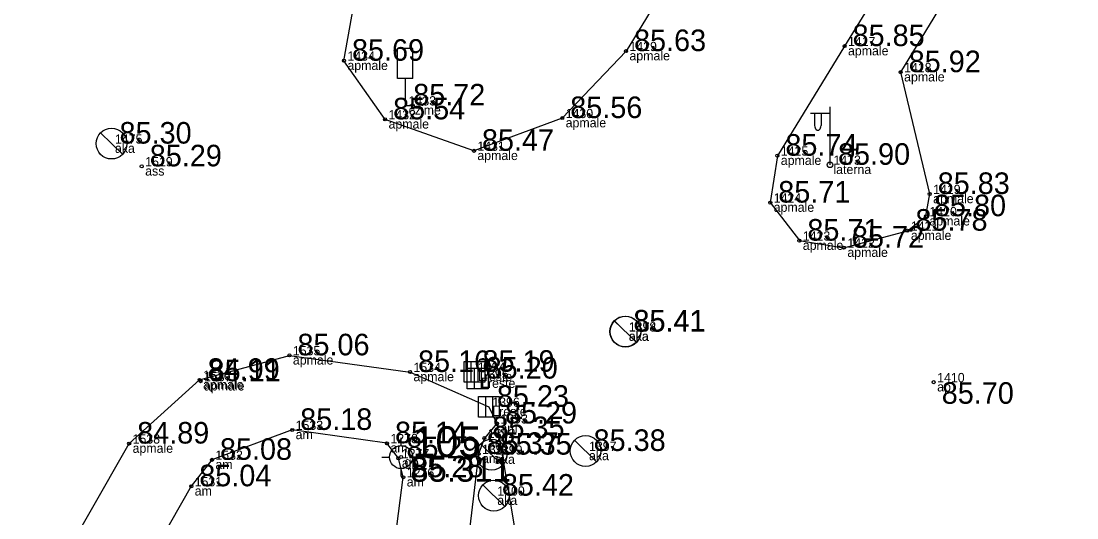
# Model space of a CAD drawing. Extents: x 614911 to 615803, y 262110 to 264311.
# Drawn here: x 615489.87 to 615524.18, y 263504.59 to 263520.72 of the extents above; entities that cross this region are included whole.
import ezdxf

# ---------------------------------------------------------------- set-up
doc = ezdxf.new("R2010")
doc.units = 0
for name, color, linetype in [('Level 12', 7, 'Continuous'), ('Level 16', 7, 'Continuous'), ('Level 19', 7, 'Continuous'), ('Level 37', 7, 'Continuous'), ('Level 44', 7, 'Continuous'), ('Level 48', 7, 'Continuous'), ('Level 53', 7, 'Continuous'), ('Level 54', 7, 'Continuous'), ('Level 57', 7, 'Continuous'), ('Level 58', 7, 'Continuous')]:
    doc.layers.add(name, color=color, linetype=linetype)

msp = doc.modelspace()

# ---------------------------------------------------------------- linework, layer by layer
at = {"layer": 'Level 12'}
for p, q in [((615492.448, 263517.088), (615493.166, 263516.392)), ((615509.143, 263510.988), (615509.861, 263510.292)), ((615509.15, 263510.983), (615509.868, 263510.287)), ((615504.797, 263506.991), (615505.515, 263506.295)), ((615507.852, 263507.11), (615508.57, 263506.414)), ((615504.871, 263505.659), (615505.589, 263504.963))]:
    msp.add_line(p, q, dxfattribs=at)
for centre in [(615492.807, 263516.74), (615509.502, 263510.64), (615509.509, 263510.635), (615508.211, 263506.762), (615505.156, 263506.643), (615505.23, 263505.311)]:
    msp.add_circle(centre, 0.5, dxfattribs=at)
at = {"layer": 'Level 16'}
for p, q in [((615502.595, 263519.825), (615502.095, 263519.825)), ((615502.095, 263518.856), (615502.095, 263519.825)), ((615502.595, 263518.856), (615502.595, 263519.825)), ((615502.595, 263518.856), (615502.095, 263518.856)), ((615502.349, 263518.856), (615502.349, 263517.978)), ((615502.349, 263517.978), (615502.664, 263517.978))]:
    msp.add_line(p, q, dxfattribs=at)
at = {"layer": 'Level 19'}
for p, q in [((615502.217, 263506.938), (615502.217, 263507.188)), ((615501.592, 263506.563), (615501.842, 263506.563)), ((615502.592, 263506.563), (615502.842, 263506.563)), ((615502.217, 263505.938), (615502.217, 263506.188))]:
    msp.add_line(p, q, dxfattribs=at)
for radius in [0.375, 0.05]:
    msp.add_circle((615502.217, 263506.563), radius, dxfattribs=at)
at = {"layer": 'Level 37'}
for points in [[(615516.164, 263530.705), (615512.022, 263523.832), (615509.525, 263519.743), (615507.452, 263517.568), (615504.583, 263516.506), (615501.696, 263517.527), (615500.36, 263519.43), (615500.743, 263521.618), (615509.136, 263535.25)], [(615505.331, 263507.653), (615504.924, 263507.18), (615504.735, 263506.666), (615503.939, 263500.01), (615504.416, 263498.924), (615505.609, 263498.295), (615506.971, 263498.275), (615508.19, 263498.495), (615518.594, 263500.546), (615529.033, 263502.579), (615542.401, 263505.157), (615548.567, 263506.422), (615549.698, 263507.269), (615549.895, 263508.502), (615549.059, 263513.135)], [(615526.135, 263499.075), (615518.177, 263497.544), (615513.224, 263496.283), (615508.96, 263494.354), (615506.959, 263493.391), (615505.012, 263492.643), (615499.231, 263491), (615498.18, 263490.854), (615493.921, 263491.94), (615491.044, 263494.684), (615489.869, 263498.786), (615490.887, 263502.64), (615493.38, 263507.002), (615495.67, 263509.069), (615498.588, 263509.866), (615502.507, 263509.325), (615505.069, 263508.195), (615505.331, 263507.653), (615506.558, 263500.366), (615517.973, 263502.492), (615528.544, 263504.401)]]:
    msp.add_lwpolyline(points, dxfattribs=at)
for points in [[(615520.426, 263524.252), (615519.091, 263523.917), (615516.626, 263519.905), (615514.443, 263516.347), (615514.212, 263514.825), (615515.158, 263513.59), (615516.606, 263513.361), (615518.67, 263513.913), (615519.271, 263514.382), (615519.393, 263515.104), (615518.45, 263519.058), (615520.777, 263522.869)], [(615498.678, 263507.445), (615496.07, 263506.474), (615495.398, 263505.615), (615493.067, 263501.527), (615492.502, 263500.109), (615492.417, 263497.555), (615492.947, 263496.239), (615493.327, 263495.784), (615494.541, 263495.306), (615496.067, 263495.065), (615499.6, 263495.729), (615500.442, 263496.233), (615501.164, 263497.228), (615502.288, 263505.909), (615502.129, 263506.525), (615501.758, 263507.012)]]:
    msp.add_lwpolyline(points, close=True, dxfattribs=at)
at = {"layer": 'Level 44'}
for p, q in [((615516.153, 263516.052), (615516.153, 263517.935)), ((615516.153, 263517.715), (615515.518, 263517.715)), ((615515.653, 263517.715), (615515.653, 263517.323)), ((615515.863, 263517.715), (615515.863, 263517.323))]:
    msp.add_line(p, q, dxfattribs=at)
msp.add_circle((615516.153, 263516.052), 0.09, dxfattribs=at)
msp.add_ellipse((615515.758, 263517.323), major_axis=(0, 0.151), ratio=0.695971, start_param=1.570796, end_param=4.712389, dxfattribs=at)
at = {"layer": 'Level 48'}
for p, q in [((615504.487, 263509.671), (615504.487, 263508.996)), ((615504.712, 263509.671), (615504.712, 263508.996)), ((615504.591, 263509.449), (615504.591, 263508.774)), ((615504.816, 263509.449), (615504.816, 263508.774)), ((615504.956, 263508.533), (615504.956, 263507.858)), ((615505.181, 263508.533), (615505.181, 263507.858))]:
    msp.add_line(p, q, dxfattribs=at)
for points in [[(615504.262, 263509.671), (615504.937, 263509.671), (615504.937, 263508.996), (615504.262, 263508.996)], [(615504.366, 263509.449), (615505.041, 263509.449), (615505.041, 263508.774), (615504.366, 263508.774)], [(615504.731, 263508.533), (615505.406, 263508.533), (615505.406, 263507.858), (615504.731, 263507.858)]]:
    msp.add_lwpolyline(points, close=True, dxfattribs=at)
at = {"layer": 'Level 57'}
for centre in [(615516.626, 263519.905), (615509.525, 263519.743), (615500.36, 263519.43), (615518.45, 263519.058), (615501.696, 263517.527), (615507.452, 263517.568), (615504.583, 263516.506), (615514.443, 263516.347), (615493.789, 263516.001), (615519.393, 263515.104), (615514.212, 263514.825), (615519.271, 263514.382), (615518.67, 263513.913), (615515.158, 263513.59), (615516.606, 263513.361), (615498.588, 263509.866), (615502.507, 263509.325), (615495.67, 263509.069), (615495.7, 263509.025), (615519.524, 263508.994), (615505.331, 263507.653), (615498.678, 263507.445), (615504.924, 263507.18), (615493.38, 263507.002), (615501.758, 263507.012), (615502.129, 263506.525), (615504.735, 263506.666), (615496.07, 263506.474), (615502.288, 263505.909), (615495.398, 263505.615)]:
    msp.add_circle(centre, 0.05, dxfattribs=at)
at = {"layer": 'Level 58'}
for centre in [(615516.626, 263519.905), (615509.525, 263519.743), (615500.36, 263519.43), (615518.45, 263519.058), (615501.696, 263517.527), (615507.452, 263517.568), (615504.583, 263516.506), (615514.443, 263516.347), (615493.789, 263516.001), (615519.393, 263515.104), (615514.212, 263514.825), (615519.271, 263514.382), (615518.67, 263513.913), (615515.158, 263513.59), (615516.606, 263513.361), (615498.588, 263509.866), (615502.507, 263509.325), (615495.67, 263509.069), (615495.7, 263509.025), (615519.524, 263508.994), (615505.331, 263507.653), (615498.678, 263507.445), (615504.924, 263507.18), (615493.38, 263507.002), (615501.758, 263507.012), (615502.129, 263506.525), (615504.735, 263506.666), (615496.07, 263506.474), (615502.288, 263505.909), (615495.398, 263505.615)]:
    msp.add_circle(centre, 0.05, dxfattribs=at)

# ---------------------------------------------------------------- texts
at = {"layer": 'Level 19'}
for s, height, p in [(' 105', 1, (615502.217, 263506.563)), (' 85.311', 0.8, (615502.217, 263505.763))]:
    msp.add_text(s, height=height, dxfattribs=at).set_placement(p)
at = {"layer": 'Level 48'}
for s, p in [(' 85.19', (615504.6, 263509.333)), (' 85.20', (615504.704, 263509.111)), (' 85.23', (615505.069, 263508.195))]:
    msp.add_text(s, height=0.7, dxfattribs=at).set_placement(p)
at = {"layer": 'Level 53'}
for s, p in [(' apmale', (615516.626, 263519.605)), (' apmale', (615509.525, 263519.443)), (' apmale', (615500.36, 263519.13)), (' apmale', (615518.45, 263518.758)), (' czime', (615502.349, 263517.678)), (' apmale', (615501.696, 263517.227)), (' apmale', (615507.452, 263517.268)), (' aka', (615492.807, 263516.44)), (' apmale', (615504.583, 263516.206)), (' apmale', (615514.443, 263516.047)), (' ass', (615493.789, 263515.701)), (' laterna', (615516.153, 263515.752)), (' apmale', (615519.393, 263514.804)), (' apmale', (615514.212, 263514.525)), (' apmale', (615519.271, 263514.082)), (' apmale', (615518.67, 263513.613)), (' apmale', (615515.158, 263513.29)), (' apmale', (615516.606, 263513.061)), (' aka', (615509.502, 263510.34)), (' aka', (615509.509, 263510.335)), (' apmale', (615498.588, 263509.566)), (' apmale', (615502.507, 263509.025)), (' Lreste', (615504.6, 263509.033)), (' apmale', (615495.67, 263508.769)), (' apmale', (615495.7, 263508.725)), (' Lreste', (615504.704, 263508.811)), (' ap', (615519.524, 263508.694)), (' Lreste', (615505.069, 263507.895)), (' am', (615505.331, 263507.353)), (' am', (615498.678, 263507.145)), (' apmale', (615493.38, 263506.702)), (' am', (615501.758, 263506.712)), (' am', (615504.924, 263506.88)), (' am', (615504.735, 263506.366)), (' aka', (615505.156, 263506.343)), (' aka', (615508.211, 263506.462)), (' am', (615496.07, 263506.174)), (' am', (615502.129, 263506.225)), (' gp', (615502.217, 263506.263)), (' am', (615502.288, 263505.609)), (' am', (615495.398, 263505.315)), (' aka', (615505.23, 263505.011))]:
    msp.add_text(s, height=0.3, dxfattribs=at).set_placement(p)
at = {"layer": 'Level 54'}
for s, p in [(' 1429', (615509.525, 263519.743)), (' 1417', (615516.626, 263519.905)), (' 1434', (615500.36, 263519.43)), (' 1418', (615518.45, 263519.058)), (' 1433', (615502.349, 263517.978)), (' 1430', (615507.452, 263517.568)), (' 1432', (615501.696, 263517.527)), (' 1475', (615492.807, 263516.74)), (' 1431', (615504.583, 263516.506)), (' 1425', (615514.443, 263516.347)), (' 1519', (615493.789, 263516.001)), (' 1473', (615516.153, 263516.052)), (' 1424', (615514.212, 263514.825)), (' 1419', (615519.393, 263515.104)), (' 1420', (615519.271, 263514.382)), (' 1421', (615518.67, 263513.913)), (' 1423', (615515.158, 263513.59)), (' 1422', (615516.606, 263513.361)), (' 1398', (615509.502, 263510.64)), (' 1474', (615509.509, 263510.635)), (' 1535', (615498.588, 263509.866)), (' 1534', (615502.507, 263509.325)), (' 1394', (615504.6, 263509.333)), (' 1536', (615495.67, 263509.069)), (' 1537', (615495.7, 263509.025)), (' 1395', (615504.704, 263509.111)), (' 1410', (615519.524, 263508.994)), (' 1396', (615505.069, 263508.195)), (' 1393', (615505.331, 263507.653)), (' 1533', (615498.678, 263507.445)), (' 1538', (615493.38, 263507.002)), (' 1278', (615501.758, 263507.012)), (' 1392', (615504.924, 263507.18)), (' 1391', (615504.735, 263506.666)), (' 1399', (615505.156, 263506.643)), (' 1397', (615508.211, 263506.762)), (' 1532', (615496.07, 263506.474)), (' 1277', (615502.129, 263506.525)), (' 1276', (615502.288, 263505.909)), (' 1531', (615495.398, 263505.615)), (' 1400', (615505.23, 263505.311))]:
    msp.add_text(s, height=0.3, dxfattribs=at).set_placement(p)
at = {"layer": 'Level 58'}
for s, p in [(' 85.85', (615516.626, 263519.905)), (' 85.63', (615509.525, 263519.743)), (' 85.69', (615500.36, 263519.43)), (' 85.92', (615518.45, 263519.058)), (' 85.72', (615502.349, 263517.978)), (' 85.54', (615501.696, 263517.527)), (' 85.56', (615507.452, 263517.568)), (' 85.30', (615492.807, 263516.74)), (' 85.47', (615504.583, 263516.506)), (' 85.74', (615514.443, 263516.347)), (' 85.29', (615493.789, 263516.001)), (' 85.90', (615516.153, 263516.052)), (' 85.83', (615519.393, 263515.104)), (' 85.71', (615514.212, 263514.825)), (' 85.80', (615519.271, 263514.382)), (' 85.78', (615518.67, 263513.913)), (' 85.71', (615515.158, 263513.59)), (' 85.72', (615516.606, 263513.361)), (' 85.41', (615509.502, 263510.64)), (' 85.41', (615509.509, 263510.635)), (' 85.06', (615498.588, 263509.866)), (' 85.16', (615502.507, 263509.325)), (' 84.99', (615495.67, 263509.069)), (' 85.11', (615495.7, 263509.025)), (' 85.70', (615519.524, 263508.294)), (' 85.29', (615505.331, 263507.653)), (' 85.18', (615498.678, 263507.445)), (' 84.89', (615493.38, 263507.002)), (' 85.14', (615501.758, 263507.012)), (' 85.35', (615504.924, 263507.18)), (' 85.29', (615502.129, 263506.525)), (' 85.37', (615504.735, 263506.666)), (' 85.35', (615505.156, 263506.643)), (' 85.38', (615508.211, 263506.762)), (' 85.08', (615496.07, 263506.474)), (' 85.28', (615502.288, 263505.909)), (' 85.04', (615495.398, 263505.615)), (' 85.42', (615505.23, 263505.311))]:
    msp.add_text(s, height=0.7, dxfattribs=at).set_placement(p)

doc.saveas('drawing.dxf')
